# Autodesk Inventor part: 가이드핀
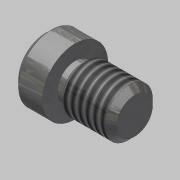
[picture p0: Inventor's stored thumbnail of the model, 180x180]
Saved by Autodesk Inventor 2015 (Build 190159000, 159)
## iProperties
Created: 2019-02
Part Number: 가이드핀
Material: 스테인리스강
Document SubType Name: Modeling
Designer: mduedu
Density: 1 g/cm^3
Appearance: 반광택
Author: mduedu
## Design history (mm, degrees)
sketch "스케치1"
  geometry: C1 r 5.5 at (0, 0); 1 further point
  constraints: 1 centre point, 1 coincident
  dimensions: "d0" = 11 diameter of C1
extrude "돌출1" new body sketch "스케치1" distance "d1" = 5; taper "d2" = 0 deg
sketch "스케치2"
  geometry: C1 r 3 at (0, 0); 1 further point
  constraints: 1 centre point, 1 coincident
  dimensions: "d3" = 6 diameter of C1
extrude "돌출2" join sketch "스케치2" distance "d4" = 1; taper "d5" = 0 deg
sketch "스케치3"
  geometry: C1 r 4 at (0, 0); 1 further point
  constraints: 1 centre point, 1 coincident
  dimensions: "d6" = 8 diameter of C1
extrude "돌출3" join sketch "스케치3" distance "d7" = 9; taper "d8" = 0 deg
chamfer "모따기1" distance "d9" = 1; stored, may be unused: second distance "d10" = 2, angle "d11" = 45 deg
feature "스레드1" dims "d12" = 10, "d13" = 0
node "솔리드1"
